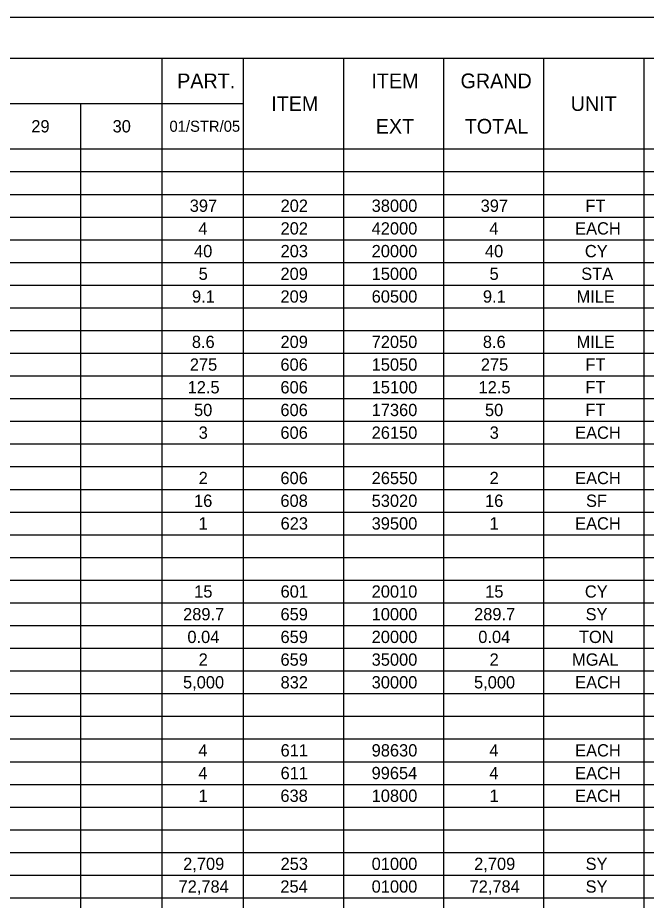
# Model space of a CAD drawing. Extents: x 0 to 34, y 0 to 22.
# Drawn here: x 7.76 to 15.52, y 11.11 to 22 of the extents above; entities that cross this region are included whole.
import ezdxf

# ---------------------------------------------------------------- set-up
doc = ezdxf.new("R2010")
doc.units = 0
for name, color, linetype in [('Default', 7, 'Continuous'), ('SH_Border', 7, 'Continuous'), ('SH_Cut_Line', 7, 'Continuous')]:
    doc.layers.add(name, color=color, linetype=linetype)

msp = doc.modelspace()

# ---------------------------------------------------------------- linework, layer by layer
at = {"layer": 'Default'}
for p, q in [((1.5, 21.5), (32.004, 21.5)), ((9.538, 21.5), (9.538, 0.5)), ((10.542, 21.5), (10.542, 0.5)), ((11.778, 21.5), (11.778, 0.5)), ((13.013, 21.5), (13.013, 0.5)), ((14.248, 21.5), (14.248, 0.5)), ((15.484, 21.5), (15.484, 0.5)), ((1.5, 20.94), (10.542, 20.94)), ((8.533, 20.94), (8.533, 0.5)), ((1.5, 20.38), (32.004, 20.38)), ((1.5, 20.1), (32.004, 20.1)), ((1.5, 19.82), (32.004, 19.82)), ((1.5, 19.54), (32.004, 19.54)), ((1.5, 19.26), (32.004, 19.26)), ((1.5, 18.98), (32.004, 18.98)), ((1.5, 18.7), (32.004, 18.7)), ((1.5, 18.42), (32.004, 18.42)), ((1.5, 18.14), (32.004, 18.14)), ((1.5, 17.86), (32.004, 17.86)), ((1.5, 17.58), (32.004, 17.58)), ((1.5, 17.3), (32.004, 17.3)), ((1.5, 17.02), (32.004, 17.02)), ((1.5, 16.74), (32.004, 16.74)), ((1.5, 16.46), (32.004, 16.46)), ((1.5, 16.18), (32.004, 16.18)), ((1.5, 15.9), (32.004, 15.9)), ((1.5, 15.62), (32.004, 15.62)), ((1.5, 15.34), (32.004, 15.34)), ((1.5, 15.06), (32.004, 15.06)), ((1.5, 14.78), (32.004, 14.78)), ((1.5, 14.5), (32.004, 14.5)), ((1.5, 14.22), (32.004, 14.22)), ((1.5, 13.94), (32.004, 13.94)), ((1.5, 13.66), (32.004, 13.66)), ((1.5, 13.38), (32.004, 13.38)), ((1.5, 13.1), (32.004, 13.1)), ((1.5, 12.82), (32.004, 12.82)), ((1.5, 12.54), (32.004, 12.54)), ((1.5, 12.26), (32.004, 12.26)), ((1.5, 11.98), (32.004, 11.98)), ((1.5, 11.7), (32.004, 11.7)), ((1.5, 11.42), (32.004, 11.42)), ((1.5, 11.14), (32.004, 11.14))]:
    msp.add_line(p, q, dxfattribs=at)
at = {"layer": 'SH_Border'}
msp.add_lwpolyline([(1.5, 21.5), (33.5, 21.5), (33.5, 0.5), (1.5, 0.5)], close=True, dxfattribs=at)
at = {"layer": 'SH_Cut_Line'}
msp.add_lwpolyline([(0, 0), (34, 0), (34, 22), (0, 22)], close=True, dxfattribs=at)

# ---------------------------------------------------------------- texts
at = {"layer": 'Default'}
for s, height, p in [('PART.', 0.1818, (9.727, 21.129)), ('ITEM', 0.1818, (12.124, 21.129)), ('GRAND', 0.1818, (13.224, 21.129)), ('ITEM', 0.1818, (10.888, 20.849)), ('UNIT', 0.1818, (14.583, 20.849)), ('29', 0.1515, (7.927, 20.584)), ('30', 0.1515, (8.93, 20.584)), ('01/STR/05', 0.1364, (9.632, 20.592)), ('EXT', 0.1818, (12.178, 20.569)), ('TOTAL', 0.1818, (13.276, 20.569)), ('397', 0.1515, (9.882, 19.604)), ('202', 0.1515, (11.003, 19.604)), ('38000', 0.1515, (12.127, 19.604)), ('397', 0.1515, (13.472, 19.604)), ('FT', 0.1515, (14.765, 19.604)), ('4', 0.152, (9.989, 19.324)), ('202', 0.1515, (11.003, 19.324)), ('42000', 0.1515, (12.127, 19.324)), ('4', 0.152, (13.579, 19.324)), ('EACH', 0.1515, (14.638, 19.324)), ('40', 0.1515, (9.935, 19.044)), ('203', 0.1515, (11.003, 19.044)), ('20000', 0.1515, (12.127, 19.044)), ('40', 0.1515, (13.525, 19.044)), ('CY', 0.1515, (14.758, 19.044)), ('5', 0.152, (9.992, 18.764)), ('209', 0.1515, (11.002, 18.764)), ('15000', 0.1515, (12.127, 18.764)), ('5', 0.152, (13.582, 18.764)), ('STA', 0.1515, (14.713, 18.764)), ('9.1', 0.1515, (9.91, 18.484)), ('209', 0.1515, (11.002, 18.484)), ('60500', 0.1515, (12.127, 18.484)), ('9.1', 0.1515, (13.5, 18.484)), ('MILE', 0.1515, (14.655, 18.484)), ('8.6', 0.1515, (9.908, 17.924)), ('209', 0.1515, (11.002, 17.924)), ('72050', 0.1515, (12.127, 17.924)), ('8.6', 0.1515, (13.499, 17.924)), ('MILE', 0.1515, (14.655, 17.924)), ('275', 0.1515, (9.883, 17.644)), ('606', 0.1515, (11.001, 17.644)), ('15050', 0.1515, (12.127, 17.644)), ('275', 0.1515, (13.474, 17.644)), ('FT', 0.1515, (14.765, 17.644)), ('12.5', 0.1515, (9.856, 17.364)), ('606', 0.1515, (11.001, 17.364)), ('15100', 0.1515, (12.127, 17.364)), ('12.5', 0.1515, (13.446, 17.364)), ('FT', 0.1515, (14.765, 17.364)), ('50', 0.1515, (9.935, 17.084)), ('606', 0.1515, (11.001, 17.084)), ('17360', 0.1515, (12.127, 17.084)), ('50', 0.1515, (13.525, 17.084)), ('FT', 0.1515, (14.765, 17.084)), ('3', 0.152, (9.992, 16.804)), ('606', 0.1515, (11.001, 16.804)), ('26150', 0.1515, (12.127, 16.804)), ('3', 0.152, (13.583, 16.804)), ('EACH', 0.1515, (14.638, 16.804)), ('2', 0.152, (9.992, 16.244)), ('606', 0.1515, (11.001, 16.244)), ('26550', 0.1515, (12.127, 16.244)), ('2', 0.152, (13.582, 16.244)), ('EACH', 0.1515, (14.638, 16.244)), ('16', 0.1515, (9.935, 15.964)), ('608', 0.1515, (11.001, 15.964)), ('53020', 0.1515, (12.127, 15.964)), ('16', 0.1515, (13.526, 15.964)), ('SF', 0.1515, (14.772, 15.964)), ('1', 0.152, (9.991, 15.684)), ('623', 0.1515, (11.003, 15.684)), ('39500', 0.1515, (12.127, 15.684)), ('1', 0.152, (13.582, 15.684)), ('EACH', 0.1515, (14.638, 15.684)), ('15', 0.1515, (9.937, 14.844)), ('601', 0.1515, (11.003, 14.844)), ('20010', 0.1515, (12.127, 14.844)), ('15', 0.1515, (13.528, 14.844)), ('CY', 0.1515, (14.758, 14.844)), ('289.7', 0.1515, (9.8, 14.564)), ('659', 0.1515, (11.002, 14.564)), ('10000', 0.1515, (12.127, 14.564)), ('289.7', 0.1515, (13.391, 14.564)), ('SY', 0.1515, (14.767, 14.564)), ('0.04', 0.1515, (9.853, 14.284)), ('659', 0.1515, (11.002, 14.284)), ('20000', 0.1515, (12.127, 14.284)), ('0.04', 0.1515, (13.443, 14.284)), ('TON', 0.1515, (14.685, 14.284)), ('2', 0.152, (9.992, 14.004)), ('659', 0.1515, (11.002, 14.004)), ('35000', 0.1515, (12.127, 14.004)), ('2', 0.152, (13.582, 14.004)), ('MGAL', 0.1515, (14.6, 14.004)), ('5,000', 0.1515, (9.799, 13.724)), ('832', 0.1515, (11.003, 13.724)), ('30000', 0.1515, (12.127, 13.724)), ('5,000', 0.1515, (13.39, 13.724)), ('EACH', 0.1515, (14.638, 13.724)), ('4', 0.152, (9.989, 12.884)), ('611', 0.1515, (11.003, 12.884)), ('98630', 0.1515, (12.127, 12.884)), ('4', 0.152, (13.579, 12.884)), ('EACH', 0.1515, (14.638, 12.884)), ('4', 0.152, (9.989, 12.604)), ('611', 0.1515, (11.003, 12.604)), ('99654', 0.1515, (12.126, 12.604)), ('4', 0.152, (13.579, 12.604)), ('EACH', 0.1515, (14.638, 12.604)), ('1', 0.152, (9.991, 12.324)), ('638', 0.1515, (11.001, 12.324)), ('10800', 0.1515, (12.127, 12.324)), ('1', 0.152, (13.582, 12.324)), ('EACH', 0.1515, (14.638, 12.324)), ('2,709', 0.1515, (9.801, 11.484)), ('253', 0.1515, (11.003, 11.484)), ('01000', 0.1515, (12.127, 11.484)), ('2,709', 0.1515, (13.392, 11.484)), ('SY', 0.1515, (14.767, 11.484)), ('72,784', 0.1515, (9.744, 11.204)), ('254', 0.1515, (11, 11.204)), ('01000', 0.1515, (12.127, 11.204)), ('72,784', 0.1515, (13.335, 11.204)), ('SY', 0.1515, (14.767, 11.204))]:
    msp.add_text(s, height=height, dxfattribs=at).set_placement(p)

doc.saveas('drawing.dxf')
